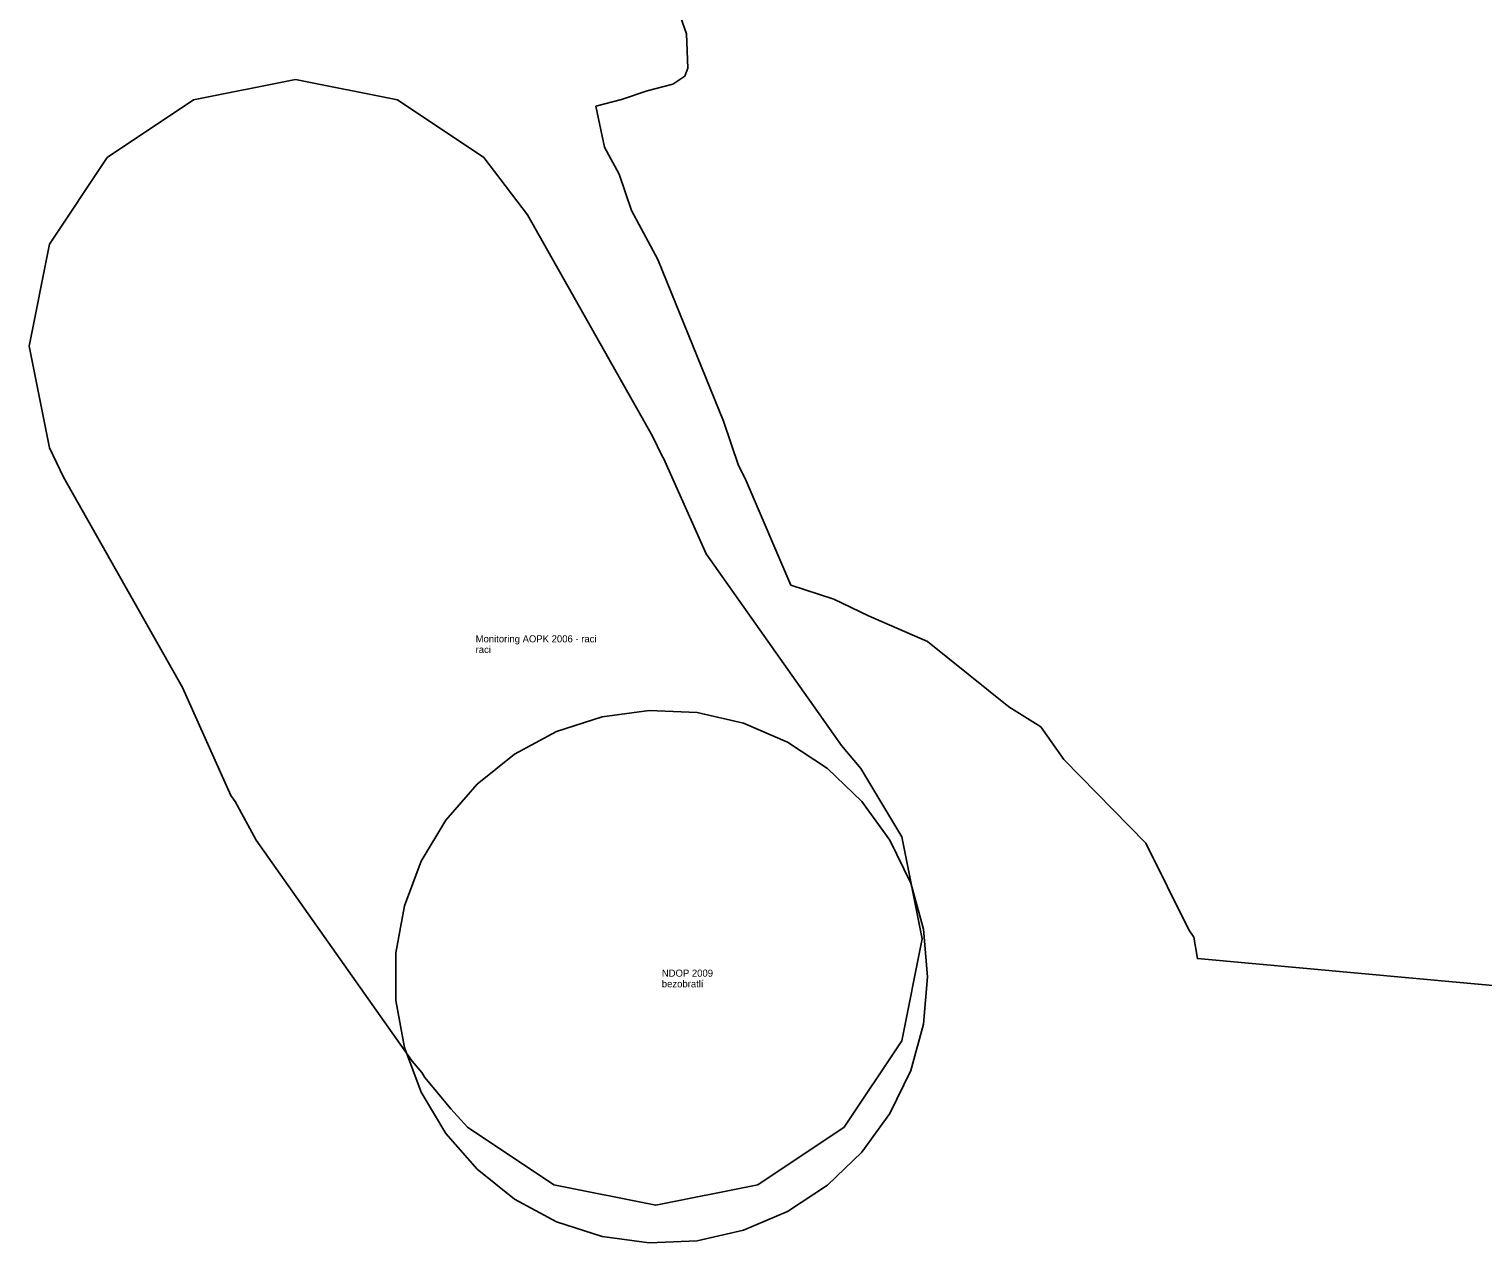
# Model space of a CAD drawing. Extents: x -477403 to -465463, y -1159182 to -1149227.
# Drawn here: x -475596.2 to -475186.8, y -1153614.1 to -1153272.5 of the extents above; entities that cross this region are included whole.
import ezdxf

# ---------------------------------------------------------------- set-up
doc = ezdxf.new("R2010")
doc.units = 0
for name, color, linetype in [('Vrstva 1', 7, 'Continuous'), ('Vrstva 10_stav', 7, 'Continuous'), ('Vrstva 2', 7, 'Continuous')]:
    doc.layers.add(name, color=color, linetype=linetype)

msp = doc.modelspace()

# ---------------------------------------------------------------- linework, layer by layer
at = {"layer": 'Vrstva 10_stav'}
msp.add_lwpolyline([(-475176.938, -1153542.375), (-475267.219, -1153534.125), (-475268.25, -1153528.125), (-475269.656, -1153526), (-475281.75, -1153501.625), (-475304.812, -1153478.125), (-475311.312, -1153468.875), (-475320.344, -1153463.25), (-475343.219, -1153444.875), (-475359.812, -1153437.625), (-475369.562, -1153433), (-475381.656, -1153429), (-475394.531, -1153399), (-475396.438, -1153395.375), (-475400.688, -1153382.875), (-475419.156, -1153337.375), (-475426.5, -1153323.625), (-475430.031, -1153313.375), (-475434.125, -1153305.75), (-475436.562, -1153294.25), (-475429.375, -1153292.375), (-475422.125, -1153289.875), (-475414.938, -1153288), (-475411.531, -1153285.75), (-475410.688, -1153283.5), (-475411.094, -1153273.875), (-475416.125, -1153259.375)], dxfattribs=at)
for points in [[(-475420.67, -1153387.107), (-475417.925, -1153392.741), (-475417.542, -1153393.296), (-475405.48, -1153420.178), (-475367.408, -1153474.117), (-475361.98, -1153480.662), (-475350.418, -1153499.84), (-475344.709, -1153528.541), (-475350.418, -1153557.243), (-475366.676, -1153581.574), (-475391.007, -1153597.832), (-475419.709, -1153603.541), (-475448.41, -1153597.832), (-475472.742, -1153581.574), (-475477.437, -1153576.42), (-475484.729, -1153567.629), (-475485.621, -1153566.148), (-475488.275, -1153562.998), (-475532.212, -1153500.749), (-475538.169, -1153489.937), (-475539.364, -1153488.204), (-475552.975, -1153457.871), (-475586.456, -1153398.611), (-475590.449, -1153390.419), (-475596.158, -1153361.718), (-475590.449, -1153333.017), (-475574.191, -1153308.685), (-475549.859, -1153292.427), (-475521.158, -1153286.718), (-475492.457, -1153292.427), (-475468.125, -1153308.685), (-475455.859, -1153324.825)], [(-475343.16, -1153539.22), (-475344.365, -1153552.612), (-475347.942, -1153565.573), (-475353.776, -1153577.687), (-475361.68, -1153588.565), (-475371.398, -1153597.857), (-475382.62, -1153605.265), (-475394.984, -1153610.549), (-475408.093, -1153613.541), (-475421.525, -1153614.144), (-475434.849, -1153612.34), (-475447.637, -1153608.185), (-475459.477, -1153601.813), (-475469.99, -1153593.43), (-475478.836, -1153583.304), (-475485.733, -1153571.761), (-475490.457, -1153559.173), (-475492.858, -1153545.943), (-475492.858, -1153532.497), (-475490.457, -1153519.267), (-475485.733, -1153506.679), (-475478.836, -1153495.136), (-475469.99, -1153485.01), (-475459.477, -1153476.627), (-475447.637, -1153470.255), (-475434.849, -1153466.1), (-475421.525, -1153464.296), (-475408.093, -1153464.899), (-475394.984, -1153467.891), (-475382.62, -1153473.175), (-475371.398, -1153480.583), (-475361.68, -1153489.875), (-475353.776, -1153500.753), (-475347.942, -1153512.867), (-475344.365, -1153525.828)]]:
    msp.add_lwpolyline(points, close=True, dxfattribs=at)

# ---------------------------------------------------------------- texts
at = {"layer": 'Vrstva 1'}
for s, p in [('raci', (-475470.433, -1153448.13)), ('raci', (-475470.433, -1153448.13)), ('bezobratlí', (-475418.009, -1153542.22)), ('bezobratlí', (-475418.009, -1153542.22))]:
    msp.add_text(s, height=2, dxfattribs=at).set_placement(p)
at = {"layer": 'Vrstva 2'}
for s, p in [('Monitoring AOPK 2006 - raci', (-475470.433, -1153445.13)), ('Monitoring AOPK 2006 - raci', (-475470.433, -1153445.13)), ('NDOP 2009', (-475418.009, -1153539.22)), ('NDOP 2009', (-475418.009, -1153539.22))]:
    msp.add_text(s, height=2, dxfattribs=at).set_placement(p)

doc.saveas('drawing.dxf')
